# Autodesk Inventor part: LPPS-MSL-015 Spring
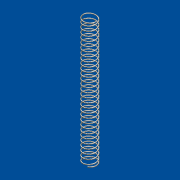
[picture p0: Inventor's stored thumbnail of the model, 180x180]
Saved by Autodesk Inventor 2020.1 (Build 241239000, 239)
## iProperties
Created: 2019-08
Part Number: LPPS-MSL-015 Spring
Material: Stainless Steel
Document SubType Name: Modeling
Designer: J. Nielson
Density: 8 g/cm^3
Appearance: Semi-Polished
Author: J. Nielson
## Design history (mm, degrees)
sketch "Sketch1"
  geometry: L1 (-4, -54.121)-(4, -54.121) reference; L2 (2.5, -91.787)-(-2.5, -91.787) reference; L3 (0, -91.787)-(0, -54.121); C1 r 0.152 at (1.905, -54.273); 1 further point
  constraints: 2 end point, 2 midpoint, 1 centre point, 1 tangent
  dimensions: "d0" = 0.3048 diameter of C1; "d1" = 1.905 distance from line of L3 C1.centre; "d2" = 37.666 distance of L3.start L3.end (derived)
coil "Coil1" sketch "Sketch1" pitch "d3" = 25.4; turns "d5" = 27; dims "d4" = 37.3612 (= d2 - d0), "d6" = 0, angle "d7" = 30 deg, angle "d8" = 180 deg, "d9" = 30 deg, "d10" = 180 deg
body "Solid1"
node "Reference1"
node "Reference2"
